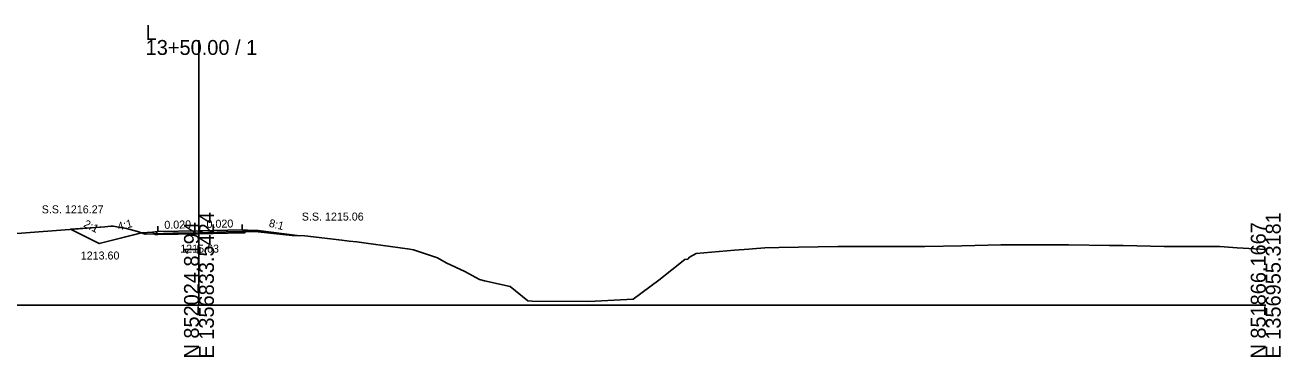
# Model space of a CAD drawing. Extents: x -26 to 3203, y -10 to 4066.
# Drawn here: x 167.4 to 402.8, y 2990.3 to 3052.6 of the extents above; entities that cross this region are included whole.
import ezdxf

# ---------------------------------------------------------------- set-up
doc = ezdxf.new("R2010")
doc.units = 0
for name, color, linetype in [('Exist Cross Section Cell', 7, 'Continuous'), ('Exist XS Center Line Elevation Label', 7, 'Continuous'), ('Exist XS Ground Line', 7, 'Continuous'), ('Prop XS Ditch Slope Text', 7, 'Continuous'), ('Prop XS Ditch Standard Text', 7, 'Continuous'), ('Prop XS Dump Level', 7, 'Continuous'), ('Prop XS Earthwork Shape', 7, 'Continuous'), ('Prop XS EOT Tick Mark', 7, 'Continuous'), ('Prop XS Finish Grade', 7, 'Continuous'), ('Prop XS Finish Grade Earthwork', 7, 'Continuous'), ('Prop XS Finish Grade Pavement', 7, 'Continuous'), ('Prop XS Pvmt Edge Slope', 7, 'Continuous'), ('Prop XS SE Text', 7, 'Continuous'), ('Prop XS Side Slope Text', 7, 'Continuous'), ('Prop XS SS Elevation Text', 7, 'Continuous'), ('Prop XS Subgrade Earthwork', 7, 'Continuous')]:
    doc.layers.add(name, color=color, linetype=linetype)

msp = doc.modelspace()

# ---------------------------------------------------------------- linework, layer by layer
at = {"layer": 'Exist Cross Section Cell'}
for p, q in [((200, 3000), (200, 3049.82)), ((0, 3000), (200, 3000)), ((200, 3000), (400, 3000))]:
    msp.add_line(p, q, dxfattribs=at)
at = {"layer": 'Exist XS Ground Line'}
for p, q in [((164.2, 3013.37), (182.38, 3014.76)), ((182.38, 3014.76), (183.49, 3014.88)), ((183.49, 3014.88), (183.92, 3014.84)), ((183.92, 3014.84), (186.43, 3014.41)), ((186.43, 3014.41), (188.47, 3013.85)), ((188.47, 3013.85), (189.91, 3013.33)), ((189.91, 3013.33), (195.09, 3013.55)), ((195.09, 3013.55), (197.26, 3013.56)), ((197.26, 3013.56), (200, 3013.63)), ((200, 3013.63), (205.1, 3013.77)), ((205.1, 3013.77), (208.27, 3013.85)), ((208.27, 3013.85), (211.13, 3013.78)), ((211.13, 3013.78), (217.48, 3013.1)), ((217.48, 3013.1), (219.85, 3013.03)), ((219.85, 3013.03), (226.81, 3012.21)), ((226.81, 3012.21), (228.19, 3012.06)), ((228.19, 3012.06), (229.57, 3011.92)), ((229.57, 3011.92), (231.37, 3011.69)), ((231.37, 3011.69), (235.9, 3011.05)), ((336.09, 3011.07), (343.01, 3011.19)), ((343.01, 3011.19), (350.32, 3011.34)), ((350.32, 3011.34), (351.1, 3011.34)), ((351.1, 3011.34), (351.46, 3011.34)), ((351.46, 3011.34), (363.03, 3011.36)), ((363.03, 3011.36), (370.69, 3011.2)), ((370.69, 3011.2), (373.29, 3011.22)), ((373.29, 3011.22), (380.94, 3011.02)), ((235.9, 3011.05), (239.55, 3010.55)), ((239.55, 3010.55), (240.2, 3010.43)), ((240.2, 3010.43), (244.75, 3008.94)), ((244.75, 3008.94), (246.36, 3007.95)), ((291.68, 3008.66), (291.97, 3009.01)), ((291.97, 3009.01), (293.22, 3009.76)), ((293.22, 3009.76), (300.38, 3010.33)), ((300.38, 3010.33), (303.08, 3010.57)), ((303.08, 3010.57), (303.79, 3010.61)), ((303.79, 3010.61), (306.06, 3010.81)), ((306.06, 3010.81), (308.71, 3010.84)), ((308.71, 3010.84), (319.76, 3011.03)), ((319.76, 3011.03), (329.11, 3011.05)), ((329.11, 3011.05), (336.09, 3011.07)), ((380.94, 3011.02), (382.17, 3011.03)), ((382.17, 3011.03), (384.54, 3011.05)), ((384.54, 3011.05), (391.39, 3011.06)), ((391.39, 3011.06), (394.64, 3010.81)), ((394.64, 3010.81), (397.97, 3010.61)), ((397.97, 3010.61), (400, 3010.49)), ((246.36, 3007.95), (249.87, 3006.32)), ((286.2, 3004.69), (291.11, 3008.6)), ((291.11, 3008.6), (291.68, 3008.66)), ((249.87, 3006.32), (252.6, 3004.87)), ((252.6, 3004.87), (253.56, 3004.59)), ((253.56, 3004.59), (258.33, 3003.53)), ((281.39, 3001.17), (286.2, 3004.69)), ((258.33, 3003.53), (261.66, 3000.83)), ((261.66, 3000.83), (262.5, 3000.8)), ((262.5, 3000.8), (272.98, 3000.7)), ((272.98, 3000.7), (274.3, 3000.8)), ((274.3, 3000.8), (281.39, 3001.17))]:
    msp.add_line(p, q, dxfattribs=at)
at = {"layer": 'Prop XS Dump Level'}
for p, q in [((192.29, 3013.84), (200, 3013.99)), ((200, 3013.99), (208.1, 3014.15))]:
    msp.add_line(p, q, dxfattribs=at)
at = {"layer": 'Prop XS Earthwork Shape'}
for points in [[(175.94, 3014.27), (182.38, 3014.76), (183.49, 3014.88), (183.92, 3014.84), (186.43, 3014.41), (188.47, 3013.85), (189.22, 3013.58), (181.29, 3011.6)], [(189.22, 3013.58), (189.91, 3013.33), (191.62, 3013.4), (191.27, 3013.75), (189.29, 3013.6)], [(200, 3013.63), (205.1, 3013.77), (208.27, 3013.85), (208.84, 3013.83), (208.63, 3013.62), (208.1, 3013.61), (200, 3013.45), (192.29, 3013.29), (191.74, 3013.28), (191.62, 3013.4), (195.09, 3013.55), (197.26, 3013.56)], [(217.48, 3013.1), (218.9, 3013.06), (211.1, 3014.03), (209.12, 3014.11), (208.84, 3013.83), (211.13, 3013.78)]]:
    msp.add_lwpolyline(points, close=True, dxfattribs=at)
at = {"layer": 'Prop XS EOT Tick Mark'}
for p, q in [((192.29, 3013.84), (192.29, 3014.84)), ((208.1, 3014.15), (208.1, 3015.15))]:
    msp.add_line(p, q, dxfattribs=at)
at = {"layer": 'Prop XS Finish Grade'}
for p, q in [((192.29, 3013.84), (191.27, 3013.75)), ((208.1, 3014.15), (209.12, 3014.11))]:
    msp.add_line(p, q, dxfattribs=at)
at = {"layer": 'Prop XS Finish Grade Earthwork'}
for p, q in [((181.29, 3011.6), (175.94, 3014.27)), ((189.29, 3013.6), (181.29, 3011.6)), ((191.27, 3013.75), (189.29, 3013.6)), ((209.12, 3014.11), (211.1, 3014.03)), ((211.1, 3014.03), (218.9, 3013.06))]:
    msp.add_line(p, q, dxfattribs=at)
at = {"layer": 'Prop XS Finish Grade Pavement'}
for p, q in [((192.29, 3013.84), (200, 3013.99)), ((200, 3013.99), (208.1, 3014.15))]:
    msp.add_line(p, q, dxfattribs=at)
at = {"layer": 'Prop XS Pvmt Edge Slope'}
for p, q in [((192.29, 3013.84), (191.74, 3013.28)), ((208.1, 3014.15), (208.63, 3013.62))]:
    msp.add_line(p, q, dxfattribs=at)
at = {"layer": 'Prop XS Subgrade Earthwork'}
for p, q in [((191.74, 3013.28), (191.27, 3013.75)), ((208.1, 3013.61), (200, 3013.45)), ((208.1, 3013.61), (208.63, 3013.62)), ((208.63, 3013.62), (209.12, 3014.11)), ((192.29, 3013.29), (191.74, 3013.28)), ((200, 3013.45), (192.29, 3013.29))]:
    msp.add_line(p, q, dxfattribs=at)

# ---------------------------------------------------------------- texts
at = {"layer": 'Exist Cross Section Cell'}
for s, p in [('L', (190, 3049.82)), ('13+50.00 / 1', (190, 3047.02))]:
    msp.add_text(s, height=2.8, dxfattribs=at).set_placement(p)
for s, p in [('E 1356833.5424', (202.8, 2990)), ('E 1356955.3181', (402.8, 2990)), ('N 852024.8194', (200, 2990)), ('N 851866.1667', (400, 2990))]:
    msp.add_text(s, height=2.8, rotation=90, dxfattribs=at).set_placement(p)
at = {"layer": 'Exist XS Center Line Elevation Label'}
msp.add_text('1215.63', height=1.5, dxfattribs=at).set_placement((196.49, 3009.89))
at = {"layer": 'Prop XS Ditch Slope Text'}
for s, rotation, p in [('4:1', 14.0362, (184.93, 3014.05)), ('8:1', 345.9638, (213.01, 3014.78))]:
    msp.add_text(s, height=1.5, rotation=rotation, dxfattribs=at).set_placement(p)
at = {"layer": 'Prop XS Ditch Standard Text'}
msp.add_text('1213.60', height=1.5, dxfattribs=at).set_placement((177.84, 3008.6))
at = {"layer": 'Prop XS Dump Level'}
for p in [(189.29, 3013.56), (211.1, 3013.99)]:
    msp.add_text('Case1', height=0.04, dxfattribs=at).set_placement(p)
at = {"layer": 'Prop XS SE Text'}
for p in [(193.52, 3014.36), (201.43, 3014.52)]:
    msp.add_text('0.020', height=1.5, rotation=1.1458, dxfattribs=at).set_placement(p)
at = {"layer": 'Prop XS Side Slope Text'}
msp.add_text('2:1', height=1.5, rotation=333.4349, dxfattribs=at).set_placement((178.23, 3014.81))
at = {"layer": 'Prop XS SS Elevation Text'}
for s, p in [('S.S. 1216.27', (170.52, 3017.27)), ('S.S. 1215.06', (219.28, 3015.91))]:
    msp.add_text(s, height=1.5, dxfattribs=at).set_placement(p)

doc.saveas('drawing.dxf')
